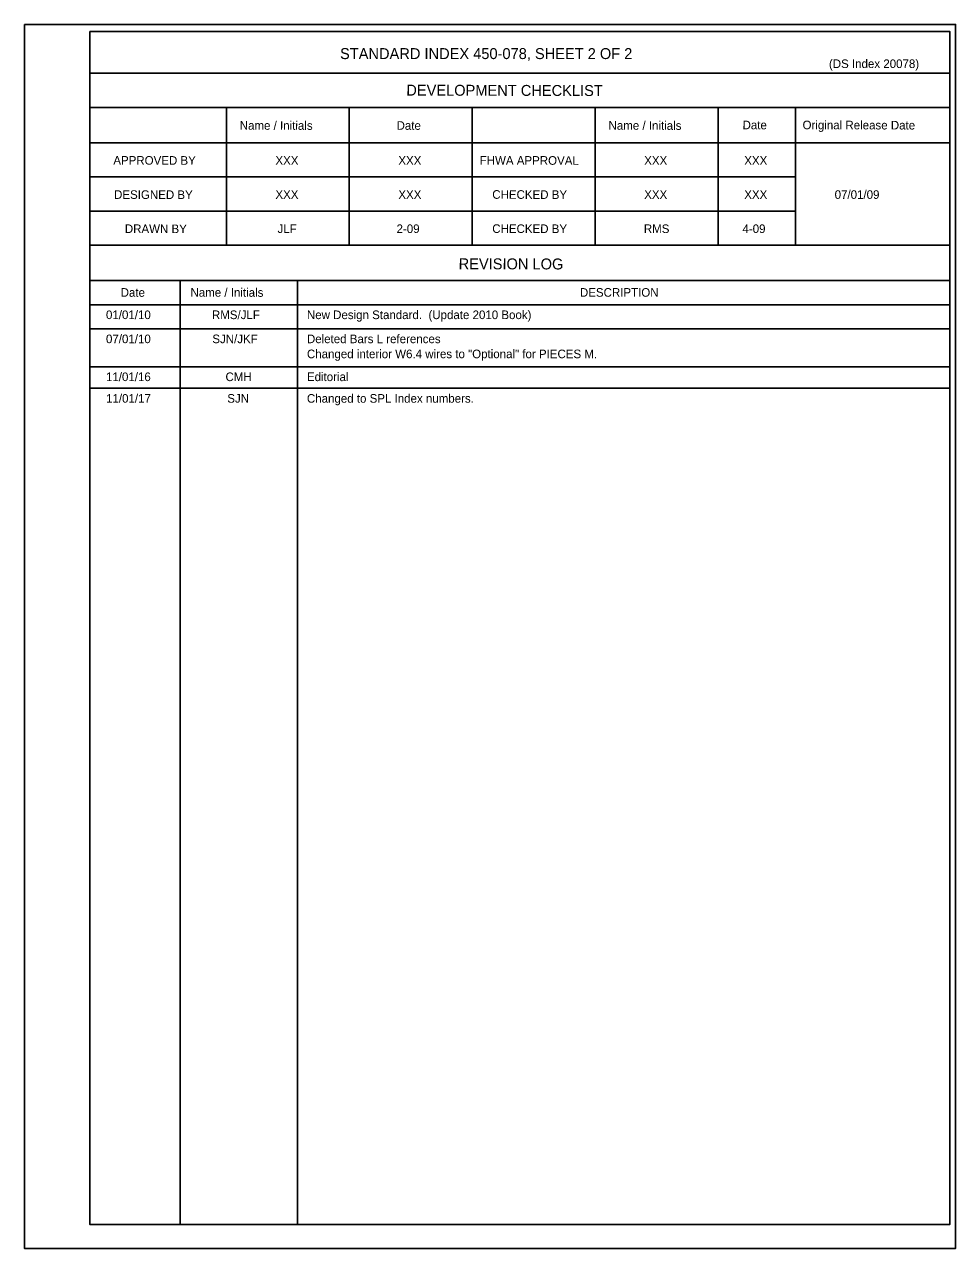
# Model space of a CAD drawing. Extents: x 4.6 to 40.7, y -0.7 to 17.4.
# Drawn here: x 29.79 to 40.7, y 2.25 to 16.59 of the extents above; entities that cross this region are included whole.
import ezdxf

# ---------------------------------------------------------------- set-up
doc = ezdxf.new("R2010")
doc.units = 0
for name, color, linetype in [('Border', 7, 'Continuous'), ('Dimension', 7, 'Continuous'), ('PlotBorder_dp', 7, 'Continuous'), ('TextStructures', 7, 'Continuous')]:
    doc.layers.add(name, color=color, linetype=linetype)

msp = doc.modelspace()

# ---------------------------------------------------------------- linework, layer by layer
at = {"layer": 'Border'}
for p, q in [((40.633, 16.015), (30.559, 16.015)), ((40.633, 15.615), (30.559, 15.615)), ((32.159, 15.615), (32.159, 14.002)), ((33.599, 15.615), (33.599, 14.002)), ((35.039, 15.615), (35.039, 14.002)), ((36.479, 15.615), (36.479, 14.002)), ((37.919, 15.615), (37.919, 14.002)), ((38.827, 15.615), (38.827, 14.002)), ((40.633, 15.202), (30.559, 15.202)), ((38.827, 14.802), (30.559, 14.802)), ((38.827, 14.402), (30.559, 14.402)), ((40.633, 14.002), (30.559, 14.002)), ((40.633, 13.588), (30.559, 13.588)), ((31.62, 13.588), (31.62, 2.534)), ((32.991, 13.588), (32.991, 2.534)), ((40.633, 13.306), (30.559, 13.306))]:
    msp.add_line(p, q, dxfattribs=at)
msp.add_lwpolyline([(30.56, 16.506), (40.633, 16.506), (40.633, 2.534), (30.56, 2.534)], close=True, dxfattribs=at)
at = {"layer": 'Dimension'}
for p, q in [((30.559, 13.024), (40.633, 13.024)), ((30.559, 12.58), (40.633, 12.58)), ((30.559, 12.327), (40.633, 12.327))]:
    msp.add_line(p, q, dxfattribs=at)
at = {"layer": 'PlotBorder_dp'}
msp.add_line((29.794, 2.254), (29.794, 2.254), dxfattribs=at)
msp.add_lwpolyline([(29.794, 16.587), (40.701, 16.587), (40.701, 2.254), (29.794, 2.254)], close=True, dxfattribs=at)

# ---------------------------------------------------------------- texts
at = {"layer": 'TextStructures'}
for s, height, p in [('STANDARD INDEX 450-078, SHEET 2 OF 2', 0.128, (33.491, 16.182)), ('(DS Index 20078)', 0.1008, (39.218, 16.077)), ('XXX', 0.1008, (32.734, 14.945)), ('XXX', 0.1008, (34.174, 14.945)), ('XXX', 0.1008, (37.054, 14.945)), ('XXX', 0.1008, (38.226, 14.945)), ('XXX', 0.1008, (32.734, 14.545)), ('XXX', 0.1008, (34.174, 14.545)), ('XXX', 0.1008, (37.054, 14.545)), ('XXX', 0.1008, (38.226, 14.545)), ('07/01/09', 0.1008, (39.285, 14.545)), ('JLF', 0.1008, (32.759, 14.145)), ('2-09', 0.1008, (34.153, 14.145)), ('RMS', 0.1008, (37.05, 14.145)), ('4-09', 0.1008, (38.205, 14.145)), ('DESCRIPTION', 0.1008, (36.301, 13.399)), ('01/01/10', 0.1008, (30.749, 13.137)), ('RMS/JLF', 0.1008, (31.99, 13.137)), ('New Design Standard.  (Update 2010 Book)', 0.1008, (33.103, 13.137)), ('07/01/10', 0.1008, (30.749, 12.855)), ('SJN/JKF', 0.1008, (31.995, 12.855)), ('Deleted Bars L references', 0.1008, (33.103, 12.855)), ('Changed interior W6.4 wires to "Optional" for PIECES M.', 0.1008, (33.103, 12.679)), ('11/01/16', 0.1008, (30.749, 12.411)), ('CMH', 0.1008, (32.149, 12.411)), ('Editorial', 0.1008, (33.103, 12.411)), ('11/01/17', 0.1008, (30.75, 12.158)), ('SJN', 0.1008, (32.17, 12.158)), ('Changed to SPL Index numbers.', 0.1008, (33.103, 12.158))]:
    msp.add_text(s, height=height, dxfattribs=at).set_placement(p)
for s, height, p in [('DEVELOPMENT CHECKLIST', 0.128, (34.267, 15.754)), ('Name / Initials', 0.1008, (32.316, 15.355)), ('Date', 0.1008, (34.153, 15.354)), ('Name / Initials', 0.1008, (36.636, 15.355)), ('Date', 0.1008, (38.206, 15.36)), ('Original Release Date', 0.1008, (38.909, 15.36)), ('APPROVED BY', 0.1008, (30.835, 14.946)), ('FHWA APPROVAL', 0.1008, (35.127, 14.946)), ('DESIGNED BY', 0.1008, (30.844, 14.545)), ('CHECKED BY', 0.1008, (35.274, 14.546)), ('DRAWN BY', 0.1008, (30.97, 14.145)), ('CHECKED BY', 0.1008, (35.274, 14.146)), ('REVISION LOG', 0.128, (34.88, 13.721)), ('Date', 0.1008, (30.921, 13.399)), ('Name / Initials', 0.1008, (31.739, 13.4))]:
    msp.add_text(s, height=height, rotation=359.8756, dxfattribs=at).set_placement(p)

doc.saveas('drawing.dxf')
